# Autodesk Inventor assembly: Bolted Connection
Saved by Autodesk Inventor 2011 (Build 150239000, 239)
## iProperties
Created: 2020-12
Part Number: Bolted Connection
Document SubType Name: Assembly
Designer: PC
ClientObjectVersion: 1
Author: PC
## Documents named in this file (3)
- C:\Users\PC\Documents\Inventor\workshop-crane-powered-by-drill\arm\Design Accelerator\Bolted Connection1.iam
- C:\Users\PC\Documents\Inventor\Content Center Files\R2011\en-US\DIN 931-1\DIN 931-1 - M14 x 75.ipt
- C:\Users\PC\Documents\Inventor\Content Center Files\R2011\en-US\DIN 555\DIN 555-5 - M14.ipt
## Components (2 placed, 2 different names)
1. DIN 931-1 - replaced by DIN EN 24014 M14 x 75:1
2. DIN 555 - replaced by DIN EN 24034 M14:1
